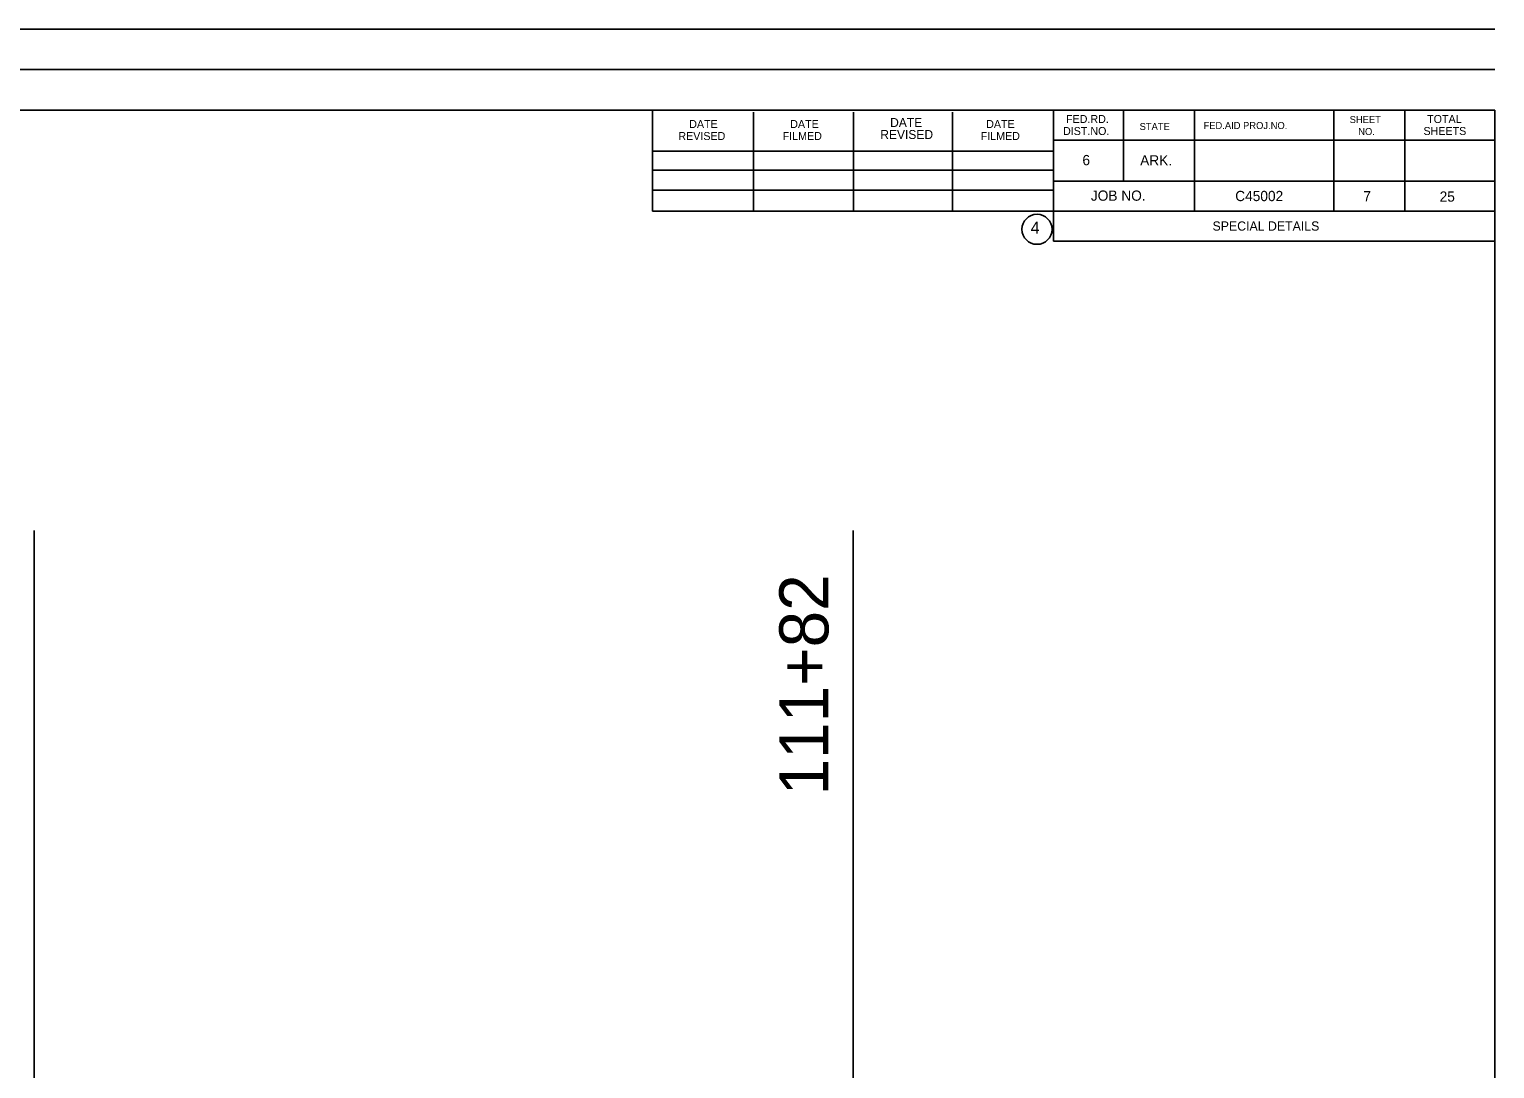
# Model space of a CAD drawing. Extents: x 1944905 to 1956777, y 763871 to 764977.
# Drawn here: x 1950934 to 1951650, y 764469 to 764977 of the extents above; entities that cross this region are included whole.
import ezdxf

# ---------------------------------------------------------------- set-up
doc = ezdxf.new("R2010")
doc.units = 0
doc.layers.add('Default', color=7, linetype='Continuous')
doc.layers.add('R_Horz Alg Annot', color=7, linetype='Continuous')

msp = doc.modelspace()

# ---------------------------------------------------------------- linework, layer by layer
at = {"layer": 'Default'}
for p, q in [((1951649.9, 764976.71), (1950031.24, 764976.71)), ((1951649.9, 764957.02), (1950031.24, 764957.02)), ((1950069, 764937.29), (1951649.9, 764937.29)), ((1951238.59, 764887.95), (1951238.59, 764937.29)), ((1951287.93, 764887.95), (1951287.93, 764936.31)), ((1951336.78, 764887.95), (1951336.78, 764936.31)), ((1951385.14, 764887.95), (1951385.14, 764936.31)), ((1951434.48, 764937.29), (1951434.48, 764873.29)), ((1951468.67, 764937.29), (1951468.67, 764902.6)), ((1951503.35, 764937.29), (1951503.35, 764887.95)), ((1951571.26, 764937.29), (1951571.26, 764887.95)), ((1951605.94, 764937.29), (1951605.94, 764887.95)), ((1951649.9, 763910.07), (1951649.9, 764937.29)), ((1951238.59, 764917.26), (1951434.48, 764917.26)), ((1951649.9, 764922.63), (1951434.48, 764922.63)), ((1951238.59, 764907.98), (1951434.48, 764907.98)), ((1951649.9, 764902.6), (1951434.48, 764902.6)), ((1951238.59, 764898.21), (1951434.48, 764898.21)), ((1951649.9, 764887.95), (1951238.59, 764887.95)), ((1951434.48, 764873.29), (1951649.91, 764873.29))]:
    msp.add_line(p, q, dxfattribs=at)
msp.add_circle((1951426.36, 764879.01), 7.33, dxfattribs=at)
at = {"layer": 'R_Horz Alg Annot'}
for points in [[(1950936.5, 764379.83), (1950936.5, 764731.83)], [(1951336.5, 764379.83), (1951336.5, 764731.83)]]:
    msp.add_lwpolyline(points, dxfattribs=at)

# ---------------------------------------------------------------- texts
at = {"layer": 'Default'}
for s, height, p in [('DATE', 3.91, (1951256.48, 764928.49)), ('DATE', 3.91, (1951305.82, 764928.49)), ('DATE', 4.396, (1951354.62, 764928.98)), ('DATE', 3.91, (1951401.52, 764928.49)), ('FED.RD.', 3.91, (1951440.52, 764930.94)), ('STATE', 3.42, (1951476.47, 764927.52)), ('FED.AID PROJ.NO.', 3.4203, (1951507.7, 764928.01)), ('SHEET', 3.42, (1951579.08, 764930.94)), ('TOTAL', 3.91, (1951616.9, 764930.94)), ('REVISED', 3.91, (1951251.18, 764922.63)), ('FILMED', 3.91, (1951302.12, 764922.63)), ('REVISED', 4.396, (1951349.8, 764923.12)), ('FILMED', 3.91, (1951398.84, 764922.63)), ('DIST.NO.', 3.91, (1951439.06, 764925.08)), ('NO.', 3.42, (1951583.26, 764925.08)), ('SHEETS', 3.91, (1951615.12, 764925.08)), ('6', 5, (1951448.55, 764910.32)), ('ARK.', 5, (1951476.75, 764910.21)), ('JOB NO.', 5, (1951452.67, 764892.97)), ('C45002', 5, (1951523.18, 764892.78)), ('7', 5, (1951585.76, 764892.68)), ('25', 5, (1951623.02, 764892.51)), ('4', 5.86, (1951423.27, 764876.89)), ('SPECIAL DETAILS', 4.5, (1951512.09, 764878.37))]:
    msp.add_text(s, height=height, dxfattribs=at).set_placement(p)
at = {"layer": 'R_Horz Alg Annot'}
msp.add_text('111+82', height=24, rotation=90, dxfattribs=at).set_placement((1951324.5, 764602.5))

doc.saveas('drawing.dxf')
